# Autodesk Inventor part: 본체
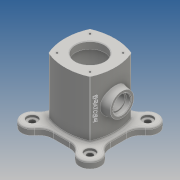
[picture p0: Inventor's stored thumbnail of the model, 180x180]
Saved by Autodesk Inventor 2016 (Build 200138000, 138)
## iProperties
Created: 2016-05
Part Number: 본체
Material: Generic
Document SubType Name: Modeling
Designer: Administrator
Density: 1 g/cm^3
Appearance: Default
Author: Administrator
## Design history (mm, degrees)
sketch "스케치1" dims "d0" = 140
  geometry: L1 (-49, 49)-(49, 49); L2 (49, 49)-(49, -49); L3 (49, -49)-(-49, -49); L4 (-49, -49)-(-49, 49); L5 (-49, 49)-(49, -49); L6 (49, 49)-(-49, -49); L7 (0, 0)-(0, 49); L8 (0, 0)-(107.625, 107.625); L9 (0, 0)-(-94.165, 94.165); L10 (0, 0)-(-132.775, -132.775); L11 (0, 0)-(113.13, -113.13); L12 (0, 0)-(0, -49); A1 r 18 centre (49.497, 49.497) between (59.754, 34.706) and (34.706, 59.754); A2 r 18 centre (-49.497, 49.497) between (-34.706, 59.754) and (-59.754, 34.706); A3 r 18 centre (-49.497, -49.497) between (-59.754, -34.706) and (-34.706, -59.754); A4 r 18 centre (49.497, -49.497) between (34.706, -59.754) and (59.754, -34.706); A5 r 25 centre (-74, 14.162) between (-49, 14.162) and (-60.503, 35.205); A6 r 25 centre (-74, -14.162) between (-60.503, -35.205) and (-49, -14.162); A7 r 25 centre (-14.162, -74) between (-14.162, -49) and (-35.205, -60.503); A8 r 25 centre (14.162, -74) between (35.205, -60.503) and (14.162, -49); A9 r 25 centre (74, -14.162) between (49, -14.162) and (60.503, -35.205); A10 r 25 centre (74, 14.162) between (60.503, 35.205) and (49, 14.162); A11 r 25 centre (14.162, 74) between (14.162, 49) and (35.205, 60.503); A12 r 25 centre (-14.162, 74) between (-35.205, 60.503) and (-14.162, 49); 1 further point
  constraints: 32 point on circle, 24 end point, 16 tangent, 12 centre point, 12 point on line, 4 midpoint, 2 parallel, 1 coincident, 1 horizontal, 1 perpendicular, 14 other
  dimensions: "d1" = 98 distance of L2.end L3.end; "d2" = 98 distance of L1.end L2.end; "d5" = 45 deg angle of L7 L8; "d6" = 45 deg angle of L9 L7; "d7" = 36 diameter of A1; "d8" = 36 diameter of A2; "d9" = 45 deg angle of L10 L12; "d10" = 45 deg angle of L12 L11; "d11" = 36 diameter of A3; "d12" = 36 diameter of A4; "d13" = 50 diameter of A5; "d14" = 50 diameter of A6; "d15" = 50 diameter of A7; "d16" = 50 diameter of A8; "d17" = 50 diameter of A9; "d18" = 50 diameter of A10; "d19" = 50 diameter of A11; "d20" = 50 diameter of A12
extrude "돌출1" new body sketch "스케치1" distance "d21" = 12; taper "d22" = 0 deg
sketch "스케치2"
  geometry: A1 r 18 centre (49.497, 49.497) between (59.754, 34.706) and (34.706, 59.754) reference; A2 r 18 centre (-49.497, 49.497) between (-34.706, 59.754) and (-59.754, 34.706) reference; A3 r 18 centre (-49.497, -49.497) between (-59.754, -34.706) and (-34.706, -59.754) reference; A4 r 18 centre (49.497, -49.497) between (34.706, -59.754) and (59.754, -34.706) reference; 5 further points
  constraints: 4 coincident
hole "구멍1" sketch "스케치2" at (-49.497, 49.497), (49.497, 49.497), (49.497, -49.497), (-49.497, -49.497) diameter "d23" = 10; stored, may be unused: countersink angle "d27" = 90 deg, drill point angle "d29" = 0 deg; dims "d24" = 6, "d25" = 18, "d26" = 4, "d28" = 8
sketch "스케치3"
  geometry: L1 (14.162, 49)-(-14.162, 49) reference; L2 (-14.162, -49)-(14.162, -49) reference; L3 (0, -49)-(0, 49); L4 (35.355, -35.355)-(-35.355, 35.355); L5 (-35.355, -35.355)-(35.355, 35.355); L6 (-25.756, 0)-(24.103, 0); A1 r 85.579 centre (42.579, 0) between (-35.355, 35.355) and (-35.355, -35.355); A2 r 85.579 centre (0, 42.579) between (-35.355, -35.355) and (35.355, -35.355); A3 r 90.136 centre (0, -47.557) between (35.355, 35.355) and (-35.355, 35.355); A4 r 85.579 centre (-42.579, 0) between (35.355, -35.355) and (35.355, 35.355); 8 further points
  constraints: 12 point on circle, 8 end point, 5 midpoint, 4 centre point, 2 coincident, 2 horizontal alignment, 2 symmetric about line, 2 vertical alignment, 1 horizontal, 1 point on line
  dimensions: "d36" = 45 deg angle of L5 L3; "d37" = 45 deg angle of L4 L3; "d38" = 100 distance of L4.start L4.end; "d39" = 100 distance of L5.start L5.end; "d42" = 86 distance of point (43, 0) point (-43, 0); "d43" = 86 distance of point (0, -43) point (0, 43)
extrude "돌출2" join sketch "스케치3" distance "d44" = 98; taper "d45" = 0 deg
sketch "스케치4"
  geometry: L1 (15.743, 61)-(-55, 61); L2 (-55, 81)-(-55, 61); L3 (-34.706, 0)-(-14.162, 0) reference; L4 (-55, 81)-(-38.425, 83.923); L5 (-43, 61)-(-55, 61); L6 (-38.425, 61)-(-38.425, 83.923); L7 (-43, 12)-(-43, 110) reference; L8 (-38.425, 61)-(-43, 61); 1 further point
  constraints: 12 end point, 2 vertical, 1 collinear, 1 horizontal, 1 parallel, 1 point on line
  dimensions: "d46" = 55 distance from line of L2 point (0, 0); "d47" = 61 distance between parallel lines of L1 L3; "d49" = 40 diameter of L2.start L1; "d54" = 100 deg angle of L7 L4; "d59" = 38.42505 distance from line of L6 point (0, 0)
revolve "회전1" sketch "스케치4" stored, may be unused: angle "d53" = 90 deg
sketch "스케치6"
  geometry: C1 r 20 at (0, 0) reference; 2 further points
  constraints: 1 coincident
hole "구멍2" sketch "스케치6" at (0, 0) diameter "d60" = 25; stored, may be unused: countersink angle "d64" = 90 deg, drill point angle "d66" = 0 deg; dims "d61" = 6, "d62" = 30, "d63" = 8, "d65" = 30
sketch "스케치7"
  geometry: L1 (0, 148.847)-(0, -38.86); L2 (35, 98)-(25, 98); L3 (35.355, 110)-(-35.355, 110) reference; L4 (35, 98)-(35, 12); L5 (35, 12)-(25, 12); L6 (14.162, 0)-(34.706, 0) reference; L7 (25, 110)-(25, 98); L8 (25, 12)-(25, 0); L9 (25, 110)-(0, 110); L10 (25, 0)-(0, 0); L11 (14.162, 0)-(-14.162, 0) reference; L12 (0, 110)-(0, 0)
  constraints: 18 end point, 4 vertical, 3 point on line, 2 collinear, 2 horizontal, 1 midpoint
  dimensions: "d68" = 12 distance between parallel lines of L2 L3; "d70" = 70 diameter of L4 L1; "d71" = 12 distance between parallel lines of L5 L6; "d72" = 50 diameter of L8 L1; "d73" = 50 diameter of L7 L1
revolve "회전2" sketch "스케치7" stored, may be unused: angle "d74" = 90 deg
sketch "스케치8" dims "d75" = 80
  geometry: L1 (0, 0)-(85.458, -85.458); L2 (0, 0)-(102.239, 102.239); L3 (0, 0)-(19.754, 0); L4 (0, 0)-(0, -20.436); C1 r 25 at (0, 0) reference; 4 further points
  constraints: 8 end point, 1 coincident, 1 horizontal, 1 point on line, 1 vertical, 8 other
  dimensions: "d76" = 45 deg angle of L3 L1; "d77" = 45 deg angle of L2 L3; "d80" = 360 deg dimension on C1.centre point (28.284, -28.284) (derived)
hole "구멍3" sketch "스케치8" at (28.284, -28.284), (28.284, 28.284), (-28.284, 28.284), (-28.284, -28.284) diameter "d82" = 3.242; stored, may be unused: countersink angle "d86" = 90 deg, drill point angle "d88" = 118 deg; dims "d83" = 7, "d84" = 30, "d85" = 8, "d87" = 10
sketch "스케치9"
  geometry: L1 (0, 0)-(13.184, 0); L2 (0, 0)-(74.821, 74.821); C1 r 25 at (0, 0) reference; C2 r 25 at (0, 0) reference; C3 r 40 at (0, 0); C4 r 1.621 at (28.284, 28.284) reference; 4 further points
  constraints: 4 end point, 2 coincident, 1 centre point, 1 horizontal, 1 point on line, 5 other
  dimensions: "d89" = 80 diameter of C3; "d90" = 45 deg angle of L1 L2; "d93" = 360 deg dimension on C1.centre point (28.284, 28.284) (derived)
hole "구멍4" sketch "스케치9" at (28.284, 28.284), (-28.284, 28.284), (-28.284, -28.284), (28.284, -28.284) diameter "d95" = 3.242; stored, may be unused: countersink angle "d99" = 90 deg, drill point angle "d101" = 118 deg; dims "d96" = 7, "d97" = 30, "d98" = 8, "d100" = 10
chamfer "모따기1" distance "d102" = 1; stored, may be unused: second distance "d103" = 2, angle "d104" = 45 deg
fillet "모깎기1" dims "d105" = 3
fillet "모깎기2" dims "d106" = 3
node "작업 평면1"
sketch "스케치10"
  geometry: L1 (42.579, 15)-(42.579, 110) reference; L2 (67.497, 0)-(34.706, 0) reference; L3 (0, 0)-(0, 163.689); L4 (97.662, 61)-(-130.641, 61); L5 (34.248, 110)-(-34.285, 110) reference; 3 further points
  constraints: 4 end point, 1 horizontal, 1 vertical, 2 other
  dimensions: "d108" = 61 distance between parallel lines of L4 L2; "d109" = 49 distance from line of L5 point (-29, 61); "d110" = 29 distance from line of L3 point (-29, 61)
feature "엠보싱1" sketch "스케치10" dims "d111" = 0.5, "d112" = 0
node "솔리드1"
